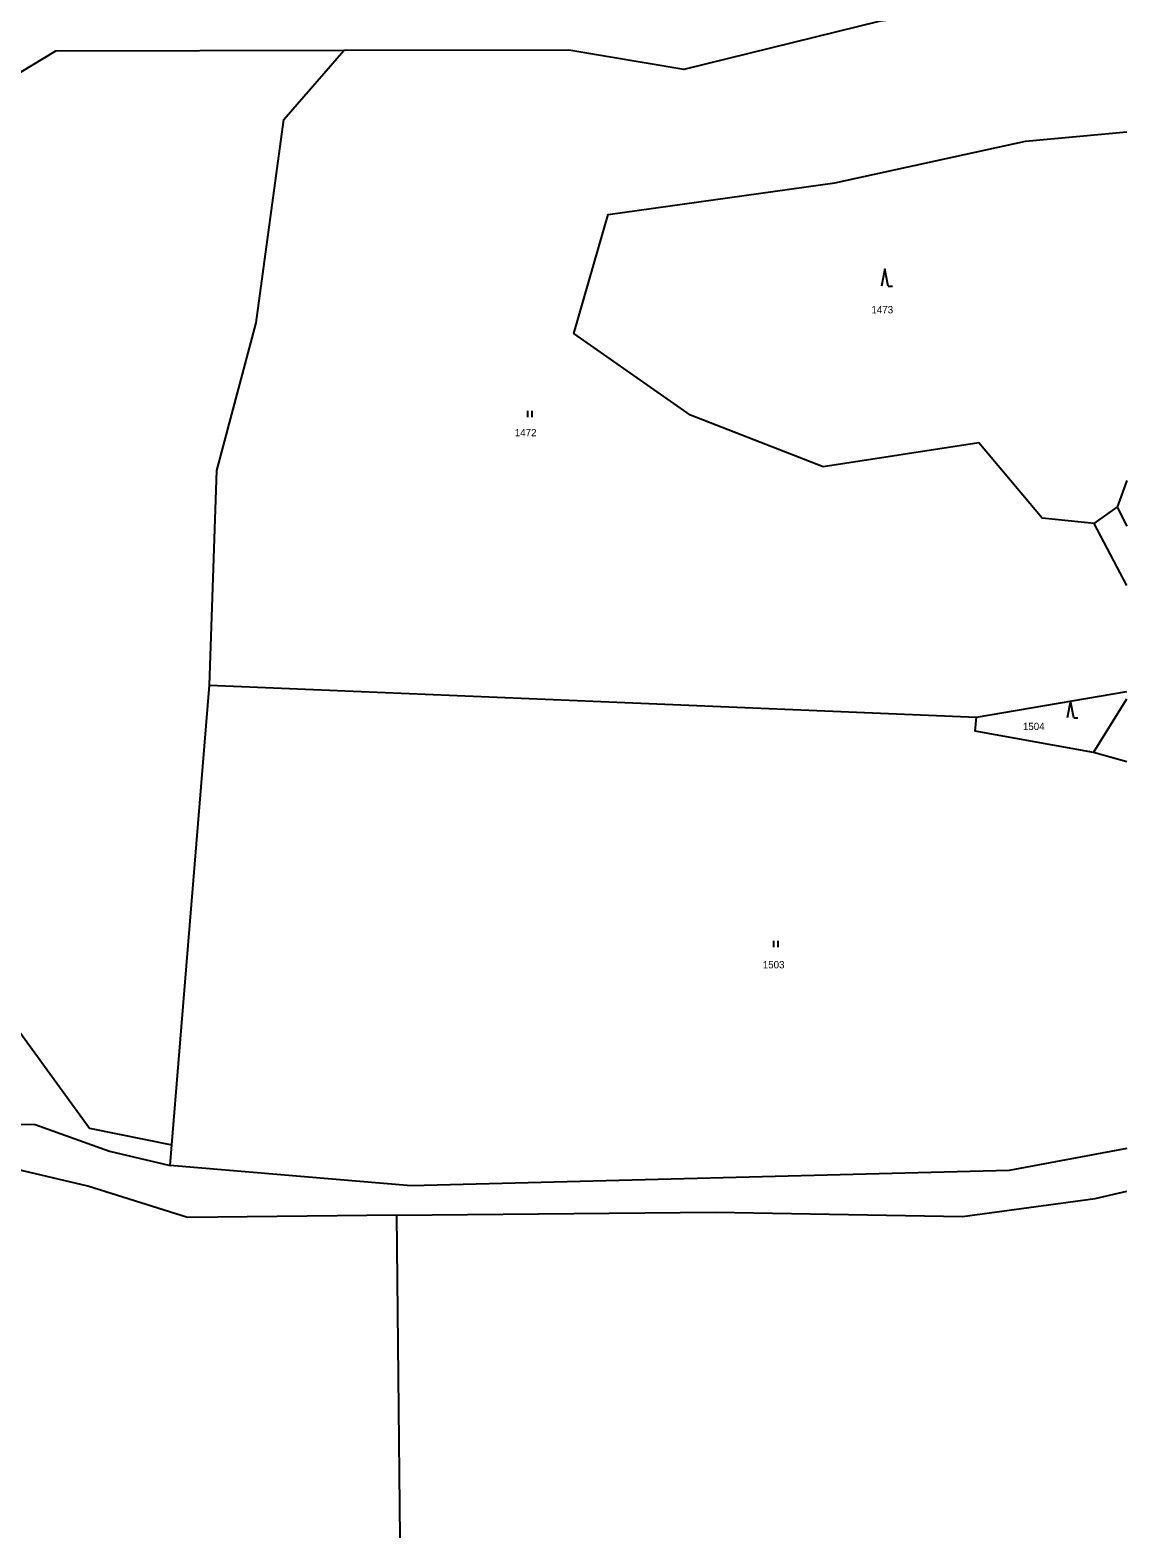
# Model space of a CAD drawing. Extents: x -520431 to -517205, y -1075927 to -1074013.
# Drawn here: x -517460.5 to -517205.1, y -1075925.4 to -1075574.4 of the extents above; entities that cross this region are included whole.
import ezdxf

# ---------------------------------------------------------------- set-up
doc = ezdxf.new("R2010")
doc.units = 0
for name, color, linetype in [('Hranice parcel', 7, 'Continuous'), ('Parcelní čísla', 7, 'Continuous'), ('Značky kultur', 7, 'Continuous')]:
    doc.layers.add(name, color=color, linetype=linetype)

msp = doc.modelspace()

# ---------------------------------------------------------------- linework, layer by layer
at = {"layer": 'Hranice parcel'}
for p, q in [((-517212.74, -1075689.25), (-517207.32, -1075685.4)), ((-517205.09, -1075703.64), (-517212.74, -1075689.25)), ((-517427.46, -1075833.88), (-517418.72, -1075726.89)), ((-517418.72, -1075726.89), (-517240.1, -1075734.31)), ((-517240.1, -1075734.31), (-517205.09, -1075728.36)), ((-517212.85, -1075742.57), (-517205.09, -1075730.06)), ((-517205.09, -1075744.68), (-517212.85, -1075742.57)), ((-517427.85, -1075838.67), (-517427.46, -1075833.88)), ((-517374.29, -1075925.35), (-517375.05, -1075850.27))]:
    msp.add_line(p, q, dxfattribs=at)
for points in [[(-517213.43, -1075566.82), (-517262.53, -1075572.25), (-517308.26, -1075583.54), (-517335.07, -1075579.03), (-517387.45, -1075579.15)], [(-517387.45, -1075579.15), (-517454.58, -1075579.31), (-517511.14, -1075613.52), (-517562.83, -1075628.57)], [(-517418.72, -1075726.89), (-517417.03, -1075676.92), (-517407.87, -1075642.53), (-517401.36, -1075595.21), (-517387.45, -1075579.15)], [(-517212.74, -1075689.25), (-517224.83, -1075687.97), (-517239.59, -1075670.48), (-517275.8, -1075676.04), (-517306.7, -1075664.04), (-517333.86, -1075644.99), (-517325.89, -1075617.33), (-517273.11, -1075609.94), (-517228.68, -1075600.21), (-517205.09, -1075598.02)], [(-517205.09, -1075679.21), (-517207.32, -1075685.4)], [(-517207.32, -1075685.4), (-517205.09, -1075689.83)], [(-517212.85, -1075742.57), (-517240.45, -1075737.53), (-517240.1, -1075734.31)], [(-517580.04, -1075822.37), (-517584.56, -1075817.38), (-517586.39, -1075799.71), (-517584.17, -1075761.45), (-517577.75, -1075757.92), (-517553.57, -1075760.25), (-517537.29, -1075766.2), (-517514.8, -1075791.53), (-517504.51, -1075794.19), (-517476.3, -1075789.28), (-517446.69, -1075830), (-517427.46, -1075833.88)], [(-517580.04, -1075822.37), (-517527.41, -1075828.28), (-517459.32, -1075829.13), (-517441.96, -1075835.35), (-517427.85, -1075838.67)], [(-517375.05, -1075850.27), (-517423.84, -1075850.75), (-517447.01, -1075843.48), (-517467.56, -1075838.71), (-517530.94, -1075834.92), (-517563.64, -1075831.53)], [(-517205.09, -1075834.69), (-517232.53, -1075839.83), (-517371.74, -1075843.42), (-517427.85, -1075838.67)], [(-517375.05, -1075850.27), (-517300.88, -1075849.55), (-517243.33, -1075850.55), (-517212.46, -1075846.39), (-517205.09, -1075844.63)]]:
    msp.add_lwpolyline(points, dxfattribs=at)
at = {"layer": 'Značky kultur'}
for p, q in [((-517261.44, -1075629.97), (-517262.19, -1075633.97)), ((-517260.69, -1075633.97), (-517261.44, -1075629.97)), ((-517260.69, -1075633.97), (-517259.69, -1075633.97)), ((-517344.58, -1075664.47), (-517344.58, -1075662.97)), ((-517343.58, -1075664.47), (-517343.58, -1075662.97)), ((-517218.22, -1075730.48), (-517218.97, -1075734.48)), ((-517217.47, -1075734.48), (-517218.22, -1075730.48)), ((-517217.47, -1075734.48), (-517216.47, -1075734.48)), ((-517287.29, -1075787.84), (-517287.29, -1075786.34)), ((-517286.29, -1075787.84), (-517286.29, -1075786.34))]:
    msp.add_line(p, q, dxfattribs=at)

# ---------------------------------------------------------------- texts
at = {"layer": 'Parcelní čísla'}
for s, p in [('1473', (-517264.57, -1075640.3)), ('1472', (-517347.61, -1075668.92)), ('1504', (-517229.3, -1075737.31)), ('1503', (-517289.87, -1075792.78))]:
    msp.add_text(s, height=1.7, dxfattribs=at).set_placement(p)

doc.saveas('drawing.dxf')
